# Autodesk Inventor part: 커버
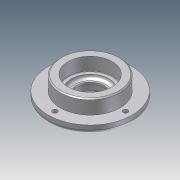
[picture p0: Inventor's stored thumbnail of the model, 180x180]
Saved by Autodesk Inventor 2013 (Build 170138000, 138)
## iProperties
Company: 한국ATC센터
Created: 2014-10
Part Number: 커버
Document SubType Name: Modeling
Designer: KYOUNG IL JANG
Density: 7.85 g/cm^3
Mass: 44.7286 g
Surface Area: 161.165 cm^2
Volume: 44.7286 cm^3
Material: 강철
Author: KYOUNG IL JANG
Revision Number: 1
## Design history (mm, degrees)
sketch "스케치1"
  geometry: C1 r 38 at (0, 0); 1 further point
  constraints: 1 centre point, 1 coincident
  dimensions: "d0" = 76 diameter of C1
extrude "돌출1" new body sketch "스케치1" distance "d1" = 7; taper "d2" = 0 deg
sketch "스케치2"
  geometry: C1 r 27 at (0, 0); 1 further point
  constraints: 1 centre point, 1 coincident
  dimensions: "d3" = 54 diameter of C1
extrude "돌출2" join sketch "스케치2" distance "d4" = 13; taper "d5" = 0 deg
sketch "스케치3"
  geometry: C1 r 20 at (0, 0); 1 further point
  constraints: 1 centre point, 1 coincident
  dimensions: "d6" = 40 diameter of C1
extrude "돌출3" join sketch "스케치3" distance "d7" = 5; taper "d8" = 0 deg
hole "구멍1" diameter "d11" = 25; stored, may be unused: countersink angle "d15" = 90 deg, drill point angle "d17" = 118 deg; dims "d9" = 10, "d10" = 10, "d12" = 6, "d13" = 32, "d14" = 8.3, "d16" = 8
hole "구멍2" diameter "d20" = 34; stored, may be unused: countersink angle "d24" = 90 deg, drill point angle "d26" = 0 deg; dims "d18" = 10, "d19" = 10, "d21" = 6, "d22" = 40, "d23" = 12, "d25" = 3
fillet "모깎기2" dims "d34" = 3
fillet "모깎기1" dims "d27" = 0.3
chamfer "모따기1" distance "d28" = 1; stored, may be unused: second distance "d29" = 2, angle "d30" = 45 deg
chamfer "모따기2" distance "d31" = 1.2; stored, may be unused: second distance "d32" = 2, angle "d33" = 30 deg
sketch "스케치4" dims "d35" = 64
  geometry: 3 further points
  constraints: 2 horizontal alignment, 1 coincident, 2 other
hole "구멍3" sketch "스케치4" at (32, 0) diameter "d36" = 4.5; stored, may be unused: countersink angle "d40" = 90 deg, drill point angle "d42" = 118 deg; dims "d37" = 6, "d38" = 8, "d39" = 4.4, "d41" = 13
node "솔리드1"
pattern_circular "원형 패턴1" dims angle "d44" = 360 deg
